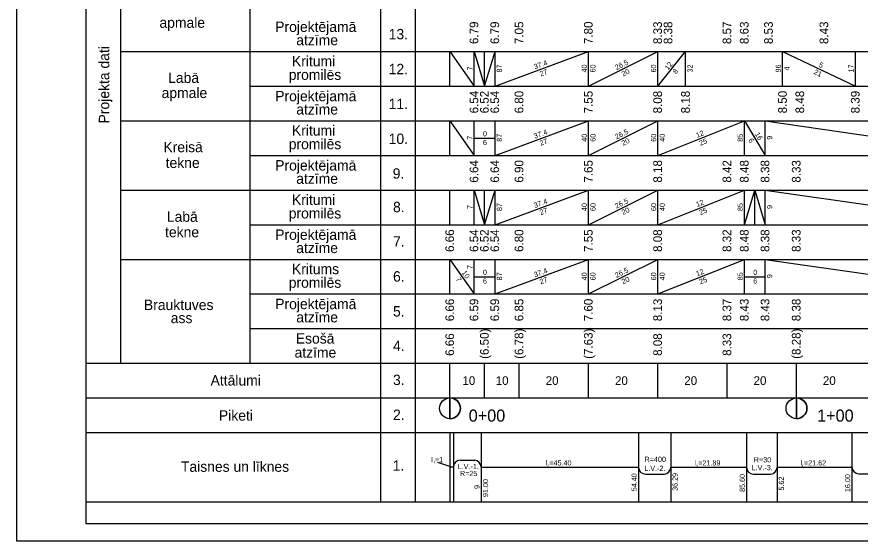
# Model space of a CAD drawing. Extents: x -465 to 136, y -149 to 148.
# Drawn here: x -464.6 to -221.2, y -149.3 to 2 of the extents above; entities that cross this region are included whole.
import ezdxf

# ---------------------------------------------------------------- set-up
doc = ezdxf.new("R2010")
doc.units = 0
for name, color, linetype in [('AA_Kritumi', 7, 'Continuous'), ('AA_M1000_A2', 7, 'Continuous'), ('AA_Piketi', 7, 'Continuous'), ('AA_Projekta_atz', 7, 'Continuous'), ('AA_Ramis', 7, 'Continuous')]:
    doc.layers.add(name, color=color, linetype=linetype)

msp = doc.modelspace()

# ---------------------------------------------------------------- linework, layer by layer
at = {"layer": 'AA_Kritumi'}
msp.add_line((-339.09, -127.98), (-343.1, -126.58), dxfattribs=at)
at = {"layer": 'AA_M1000_A2'}
for p, q in [((-464.59, -149.32), (-464.59, 147.68)), ((-444.59, -144.32), (-444.59, 142.68)), ((130.72, -144.32), (-444.59, -144.32)), ((135.72, -149.32), (-464.59, -149.32))]:
    msp.add_line(p, q, dxfattribs=at)
at = {"layer": 'AA_Ramis'}
for p, q in [((-444.6, -137.98), (-444.6, 72.02)), ((-434.6, -97.98), (-434.6, 72.02)), ((-359.6, 72.02), (-359.6, -137.98)), ((-349.6, 72.02), (-349.6, -137.98)), ((-397.23, -97.98), (-397.23, 52.02)), ((-434.6, -7.98), (-349.6, -7.98)), ((-349.6, -7.98), (-54.28, -7.98)), ((-339.59, -17.98), (-339.59, -7.98)), ((-339.59, -7.98), (-332.59, -17.98)), ((-332.59, -17.98), (-332.59, -7.98)), ((-332.59, -7.98), (-329.59, -17.98)), ((-329.59, -17.98), (-329.59, -7.98)), ((-329.59, -17.98), (-326.59, -7.98)), ((-326.59, -17.98), (-326.59, -7.98)), ((-326.59, -17.98), (-299.59, -7.98)), ((-299.59, -17.98), (-299.59, -7.98)), ((-299.59, -17.98), (-279.59, -7.98)), ((-279.59, -17.98), (-279.59, -7.98)), ((-279.59, -17.98), (-271.59, -7.98)), ((-271.59, -17.98), (-271.59, -7.98)), ((-243.59, -17.98), (-243.59, -7.98)), ((-243.59, -7.98), (-222.59, -17.98)), ((-222.59, -17.98), (-222.59, -7.98)), ((-397.23, -17.98), (-349.6, -17.98)), ((-349.6, -17.98), (-54.28, -17.98)), ((-434.6, -27.98), (-349.6, -27.98)), ((-349.6, -27.98), (-54.28, -27.98)), ((-339.59, -37.98), (-339.59, -27.98)), ((-339.59, -27.98), (-332.59, -37.98)), ((-332.59, -37.98), (-332.59, -27.98)), ((-326.59, -37.98), (-326.59, -27.98)), ((-326.59, -37.98), (-299.59, -27.98)), ((-299.59, -37.98), (-299.59, -27.98)), ((-299.59, -37.98), (-279.59, -27.98)), ((-279.59, -37.98), (-279.59, -27.98)), ((-279.59, -37.98), (-254.59, -27.98)), ((-254.59, -37.98), (-254.59, -27.98)), ((-254.59, -27.98), (-248.59, -37.98)), ((-248.59, -37.98), (-248.59, -27.98)), ((-248.59, -27.98), (-179.59, -37.98)), ((-332.59, -32.98), (-326.59, -32.98)), ((-397.23, -37.98), (-349.6, -37.98)), ((-349.6, -37.98), (-54.28, -37.98)), ((-434.6, -47.98), (-349.6, -47.98)), ((-349.6, -47.98), (-54.28, -47.98)), ((-339.59, -57.98), (-339.59, -47.98)), ((-332.59, -57.98), (-332.59, -47.98)), ((-332.59, -47.98), (-329.59, -57.98)), ((-329.59, -57.98), (-326.59, -47.98)), ((-329.59, -57.98), (-329.59, -47.98)), ((-326.59, -57.98), (-326.59, -47.98)), ((-326.59, -57.98), (-299.59, -47.98)), ((-299.59, -57.98), (-299.59, -47.98)), ((-299.59, -57.98), (-279.59, -47.98)), ((-279.59, -57.98), (-279.59, -47.98)), ((-279.59, -57.98), (-254.59, -47.98)), ((-254.59, -57.98), (-254.59, -47.98)), ((-254.59, -57.98), (-251.59, -47.98)), ((-251.59, -57.98), (-251.59, -47.98)), ((-251.59, -47.98), (-248.59, -57.98)), ((-248.59, -57.98), (-248.59, -47.98)), ((-248.59, -47.98), (-179.59, -57.98)), ((-397.23, -57.98), (-349.6, -57.98)), ((-349.6, -57.98), (-54.28, -57.98)), ((-434.6, -67.98), (-349.6, -67.98)), ((-349.6, -67.98), (-54.28, -67.98)), ((-339.59, -77.98), (-339.59, -67.98)), ((-339.59, -67.98), (-332.59, -77.98)), ((-332.59, -77.98), (-332.59, -67.98)), ((-326.59, -77.98), (-326.59, -67.98)), ((-326.59, -77.98), (-299.59, -67.98)), ((-299.59, -77.98), (-299.59, -67.98)), ((-299.59, -77.98), (-279.59, -67.98)), ((-279.59, -77.98), (-279.59, -67.98)), ((-279.59, -77.98), (-254.59, -67.98)), ((-254.59, -77.98), (-254.59, -67.98)), ((-248.59, -77.98), (-248.59, -67.98)), ((-248.59, -67.98), (-179.59, -77.98)), ((-332.59, -72.98), (-326.59, -72.98)), ((-254.59, -72.98), (-248.59, -72.98)), ((-397.23, -77.98), (-349.6, -77.98)), ((-349.6, -77.98), (-54.28, -77.98)), ((-397.23, -87.98), (-349.6, -87.98)), ((-349.6, -87.98), (-54.28, -87.98)), ((-444.6, -97.98), (-349.6, -97.98)), ((-349.6, -97.98), (-54.28, -97.98)), ((-339.59, -107.98), (-339.59, -97.98)), ((-329.59, -107.98), (-329.59, -97.98)), ((-319.59, -107.98), (-319.59, -97.98)), ((-299.59, -107.98), (-299.59, -97.98)), ((-279.59, -107.98), (-279.59, -97.98)), ((-259.59, -107.98), (-259.59, -97.98)), ((-239.59, -107.98), (-239.59, -97.98)), ((-444.6, -107.98), (-349.6, -107.98)), ((-349.6, -107.98), (-54.28, -107.98)), ((-339.59, -113.98), (-339.59, -107.98)), ((-239.59, -113.98), (-239.59, -107.98)), ((-444.6, -117.98), (-349.6, -117.98)), ((-349.6, -117.98), (-54.28, -117.98)), ((-339.59, -117.98), (-339.59, -137.98)), ((-338.59, -117.98), (-338.59, -137.98)), ((-330.59, -117.98), (-330.59, -137.98)), ((-285.19, -117.98), (-285.19, -137.98)), ((-275.88, -117.98), (-275.88, -137.98)), ((-253.99, -117.98), (-253.99, -137.98)), ((-245.21, -117.98), (-245.21, -137.98)), ((-223.59, -117.98), (-223.59, -137.98)), ((-336.61, -125.98), (-332.46, -125.98)), ((-338.59, -127.98), (-339.59, -127.98)), ((-330.59, -127.98), (-285.19, -127.98)), ((-275.88, -127.98), (-253.99, -127.98)), ((-245.21, -127.98), (-223.59, -127.98)), ((-283.19, -129.98), (-277.73, -129.98)), ((-251.99, -129.98), (-247.06, -129.98)), ((-221.59, -129.85), (-212.61, -129.85)), ((-444.6, -137.98), (-54.28, -137.98))]:
    msp.add_line(p, q, dxfattribs=at)
for points in [[(-339.59, -107.98), (-339.59, -113.98)], [(-239.59, -107.98), (-239.59, -113.98)]]:
    msp.add_lwpolyline(points, dxfattribs=at)
for centre in [(-339.59, -110.98), (-239.59, -110.98)]:
    msp.add_circle(centre, 3, dxfattribs=at)
for centre, radius, start, end in [((-339.59, -110.98), 3, 0, 90), ((-239.59, -110.98), 3, 0, 90), ((-339.59, -110.98), 3, 270, 0), ((-239.59, -110.98), 3, 270, 0), ((-336.61, -127.98), 2, 90, 180), ((-332.61, -127.97), 2, 359.8436, 85.7657), ((-283.19, -127.98), 2, 180, 270), ((-277.88, -127.99), 2, 274.2343, 0.1564), ((-251.99, -127.98), 2, 180, 270), ((-247.21, -127.99), 2, 274.2343, 0.1564), ((-221.59, -127.85), 2, 180, 270)]:
    msp.add_arc(centre, radius, start, end, dxfattribs=at)

# ---------------------------------------------------------------- texts
at = {"layer": 'AA_Kritumi'}
for s, rotation, p in [('87', 90, (-324.59, -14.04)), ('37.4', 20.3231, (-315.09, -13.19)), ('40', 90, (-300.09, -14.04)), ('60', 90, (-297.59, -14.04)), ('26.5', 26.5651, (-291.53, -13.39)), ('60', 90, (-280.09, -14.04)), ('12', 51.3402, (-276.64, -13.49)), ('32', 90, (-269.59, -14.04)), ('96', 90, (-244.09, -14.04)), ('5', 334.5367, (-233.32, -12.32)), ('17', 90, (-223.09, -14.04)), ('7', 90, (-333.09, -13.47)), ('27', 20.3231, (-313.39, -15.22)), ('20', 26.5651, (-289.64, -15.24)), ('8', 51.3402, (-274.33, -14.61)), ('4', 90, (-241.59, -13.49)), ('21', 334.5367, (-234.75, -14.4)), ('37.4', 20.3231, (-315.09, -33.19)), ('26.5', 26.5651, (-291.53, -33.39)), ('12', 21.8014, (-268.26, -32.91)), ('16', 300.9638, (-251.71, -31.82)), ('7', 90, (-333.09, -33.47)), ('87', 90, (-324.59, -34.04)), ('27', 20.3231, (-313.39, -35.22)), ('40', 90, (-300.09, -34.04)), ('60', 90, (-297.59, -34.04)), ('20', 26.5651, (-289.64, -35.24)), ('60', 90, (-280.09, -34.04)), ('40', 90, (-277.59, -34.04)), ('25', 21.8014, (-267.33, -35.23)), ('85', 90, (-255.09, -34.04)), ('6', 300.9638, (-253.56, -33.59)), ('9', 90, (-246.59, -33.44)), ('37.4', 20.3231, (-315.09, -53.19)), ('26.5', 26.5651, (-291.53, -53.39)), ('12', 21.8014, (-268.26, -52.91)), ('7', 90, (-333.09, -53.47)), ('87', 90, (-324.59, -54.04)), ('27', 20.3231, (-313.39, -55.22)), ('40', 90, (-300.09, -54.04)), ('60', 90, (-297.59, -54.04)), ('20', 26.5651, (-289.64, -55.24)), ('60', 90, (-280.09, -54.04)), ('40', 90, (-277.59, -54.04)), ('25', 21.8014, (-267.33, -55.23)), ('85', 90, (-255.09, -54.04)), ('9', 90, (-246.59, -53.44)), ('7', 90, (-333.09, -70.79)), ('37.4', 20.3231, (-315.09, -73.19)), ('26.5', 26.5651, (-291.53, -73.39)), ('7', 304.992, (-338.01, -73.73)), ('10', 304.992, (-336.29, -71.83)), ('87', 90, (-324.59, -74.04)), ('40', 90, (-300.09, -74.04)), ('60', 90, (-297.59, -74.04)), ('60', 90, (-280.09, -74.04)), ('40', 90, (-277.59, -74.04)), ('12', 21.8014, (-268.26, -72.91)), ('85', 90, (-255.09, -74.04)), ('9', 90, (-246.59, -73.44)), ('27', 20.3231, (-313.39, -75.22)), ('20', 26.5651, (-289.64, -75.24)), ('25', 21.8014, (-267.33, -75.23)), ('l =45.40', 360, (-311.95, -127.48)), ('l =21.89', 360, (-268.97, -127.48)), ('l =21.62', 360, (-238.46, -127.48)), ('54.40', 90, (-285.69, -134.91)), ('36.29', 90, (-273.88, -134.82)), ('85.60', 90, (-254.49, -135.11)), ('5.62', 90, (-243.21, -134.73)), ('16.00', 90, (-224.09, -135.17)), ('9', 90, (-331.09, -134.25)), ('91.00', 90, (-328.59, -136.6))]:
    msp.add_text(s, height=1.5, rotation=rotation, dxfattribs=at).set_placement(p)
for s, height, p in [('0', 1.5, (-330.08, -32.48)), ('6', 1.5, (-330.08, -34.98)), ('0', 1.5, (-330.08, -72.48)), ('0', 1.5, (-252.08, -72.48)), ('6', 1.5, (-330.08, -74.98)), ('6', 1.5, (-252.08, -74.98)), ('l =1', 1.5, (-344.99, -126.58)), ('1', 0.7, (-344.34, -126.91)), ('R=400', 1.5, (-283.44, -126.46)), ('R=30', 1.5, (-251.9, -126.59)), ('L.V.-1.', 1.5, (-337.37, -128.53)), ('2', 0.7, (-311.59, -127.92)), ('L.V.-2.', 1.5, (-283.52, -129.06)), ('3', 0.7, (-268.62, -127.92)), ('L.V.-3.', 1.5, (-252.55, -128.86)), ('4', 0.7, (-238.12, -127.92)), ('R=25', 1.5, (-336.71, -130.54))]:
    msp.add_text(s, height=height, dxfattribs=at).set_placement(p)
at = {"layer": 'AA_Piketi'}
for s, height, p in [('10', 2.5, (-336.01, -104.23)), ('10', 2.5, (-326.41, -104.23)), ('20', 2.5, (-311.98, -104.23)), ('20', 2.5, (-291.98, -104.23)), ('20', 2.5, (-271.98, -104.23)), ('20', 2.5, (-251.98, -104.23)), ('20', 2.5, (-231.98, -104.23)), ('0+00', 3.5, (-334.19, -114.83)), ('1+00', 3.5, (-233.64, -114.83))]:
    msp.add_text(s, height=height, dxfattribs=at).set_placement(p)
at = {"layer": 'AA_Projekta_atz'}
for s, p in [('6.79', (-331.42, -5.84)), ('6.79', (-325.42, -5.84)), ('7.05', (-318.42, -5.84)), ('7.80', (-298.42, -5.84)), ('8.33', (-278.42, -5.84)), ('8.38', (-275.42, -5.84)), ('8.57', (-258.42, -5.84)), ('8.63', (-253.42, -5.84)), ('8.53', (-246.42, -5.84)), ('8.43', (-230.42, -5.84)), ('6.54', (-331.42, -25.84)), ('6.54', (-325.42, -25.84)), ('6.80', (-318.42, -25.84)), ('8.50', (-242.38, -25.84)), ('6.52', (-328.42, -25.84)), ('7.55', (-298.42, -25.84)), ('8.08', (-278.42, -25.84)), ('8.18', (-270.38, -25.84)), ('8.48', (-237.38, -25.84)), ('8.39', (-221.38, -25.84)), ('6.64', (-331.42, -45.84)), ('6.64', (-325.42, -45.84)), ('6.90', (-318.42, -45.84)), ('7.65', (-298.42, -45.84)), ('8.18', (-278.42, -45.84)), ('8.42', (-258.42, -45.84)), ('8.48', (-253.42, -45.84)), ('8.38', (-247.42, -45.84)), ('8.33', (-238.42, -45.84)), ('6.66', (-338.42, -65.84)), ('6.54', (-331.42, -65.84)), ('6.52', (-328.42, -65.84)), ('6.54', (-325.42, -65.84)), ('6.80', (-318.42, -65.84)), ('7.55', (-298.42, -65.84)), ('8.08', (-278.42, -65.84)), ('8.32', (-258.42, -65.84)), ('8.48', (-253.42, -65.84)), ('8.38', (-247.42, -65.84)), ('8.33', (-238.42, -65.84)), ('6.66', (-338.42, -85.84)), ('6.59', (-331.42, -85.84)), ('6.59', (-325.42, -85.84)), ('6.85', (-318.42, -85.84)), ('7.60', (-298.42, -85.84)), ('8.13', (-278.42, -85.84)), ('8.37', (-258.42, -85.84)), ('8.43', (-253.42, -85.84)), ('8.43', (-247.42, -85.84)), ('8.38', (-238.42, -85.84)), ('6.66', (-338.42, -95.84)), ('(6.50)', (-328.42, -96.71)), ('(6.78)', (-318.42, -96.71)), ('(7.63)', (-298.42, -96.71)), ('8.08', (-278.42, -95.84)), ('8.33', (-258.42, -95.84)), ('(8.28)', (-238.42, -96.71))]:
    msp.add_text(s, height=2.5, rotation=90, dxfattribs=at).set_placement(p)
at = {"layer": 'AA_Ramis'}
for s, p in [('apmale', (-423.44, -1.15)), ('Projektējamā', (-390.03, -2.35)), ('13.', (-357.28, -4.47)), ('atzīme', (-383.96, -6.18)), ('Kritumi', (-385.2, -12.26)), ('12.', (-357.28, -14.54)), ('Labā', (-420.94, -17.06)), ('promilēs', (-386.13, -16.18)), ('apmale', (-422.81, -21.42)), ('Projektējamā', (-390.03, -22.35)), ('11.', (-357.28, -24.61)), ('atzīme', (-383.96, -26.18)), ('Kritumi', (-385.2, -32.26)), ('Kreisā', (-422.3, -37.06)), ('promilēs', (-386.13, -36.18)), ('10.', (-357.28, -34.69)), ('tekne', (-421.65, -41.6)), ('Projektējamā', (-390.03, -42.35)), ('atzīme', (-383.96, -46.18)), ('9.', (-356.12, -44.69)), ('Kritumi', (-385.2, -52.26)), ('promilēs', (-386.13, -56.18)), ('8.', (-356.03, -54.36)), ('Labā', (-421.3, -57.15)), ('tekne', (-421.83, -61.6)), ('Projektējamā', (-390.03, -62.35)), ('atzīme', (-383.96, -66.18)), ('7.', (-356.03, -64.34)), ('Kritums', (-385.2, -72.26)), ('6.', (-356.03, -74.41)), ('promilēs', (-386.13, -76.18)), ('Brauktuves', (-427.92, -82.62)), ('Projektējamā', (-390.03, -82.35)), ('5.', (-356.03, -84.49)), ('ass', (-420.18, -86.39)), ('atzīme', (-383.96, -86.18)), ('Esošā', (-384.09, -92.31)), ('4.', (-356.03, -94.47)), ('atzīme', (-384.45, -96.36)), ('Attālumi', (-408.68, -104.4)), ('3.', (-356.03, -104.27)), ('Piketi', (-406.28, -114.53)), ('2.', (-356.03, -114.35)), ('Taisnes un līknes', (-417.24, -129.31)), ('1.', (-356.12, -128.97))]:
    msp.add_text(s, height=3, dxfattribs=at).set_placement(p)
msp.add_text('Projekta dati', height=3, rotation=90, dxfattribs=at).set_placement((-437.94, -28.74))

doc.saveas('drawing.dxf')
